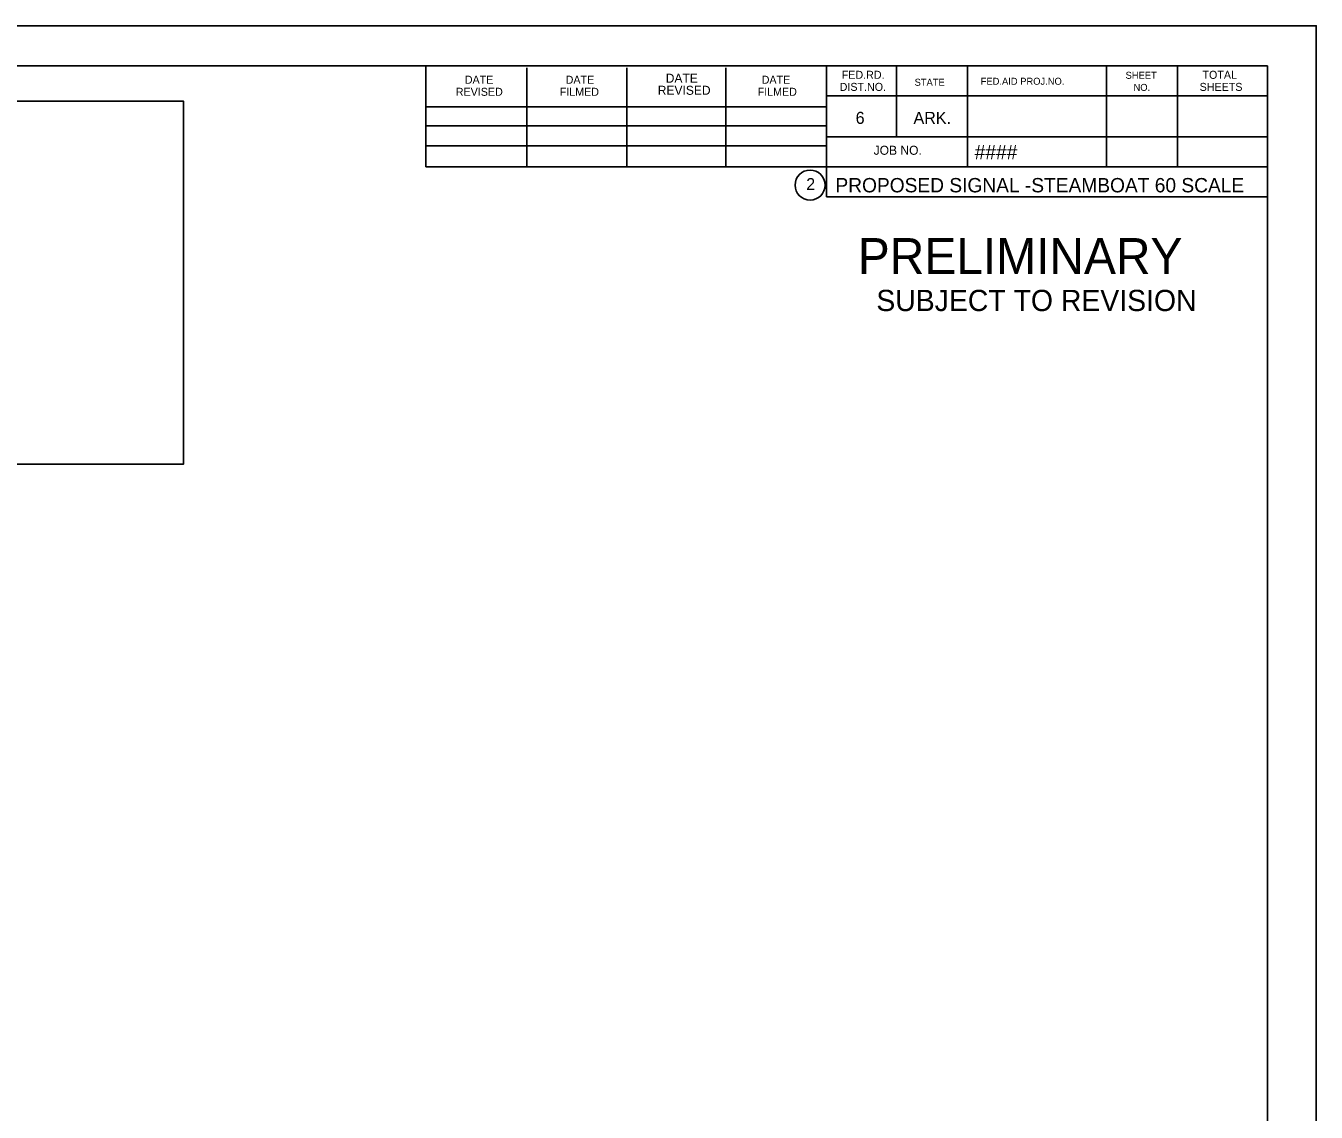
# Model space of a CAD drawing. Extents: x 660636 to 661659, y 641779 to 643841.
# Drawn here: x 661280.2 to 661658.6, y 642605.7 to 642924 of the extents above; entities that cross this region are included whole.
import ezdxf

# ---------------------------------------------------------------- set-up
doc = ezdxf.new("R2010")
doc.units = 0
for name, color, linetype in [('Default', 7, 'Continuous'), ('R_Border', 7, 'Continuous'), ('R_Border Prem', 7, 'Continuous'), ('R_No Plot', 7, 'Continuous')]:
    doc.layers.add(name, color=color, linetype=linetype)

msp = doc.modelspace()

# ---------------------------------------------------------------- linework, layer by layer
at = {"layer": 'Default'}
msp.add_lwpolyline([(661077.35, 642795.58), (661326.48, 642795.58), (661326.48, 642901.91), (661077.35, 642901.91)], close=True, dxfattribs=at)
at = {"layer": 'R_Border'}
for p, q in [((660695.76, 642912.31), (661644.3, 642912.31)), ((661397.52, 642882.67), (661397.52, 642912.31)), ((661427.09, 642882.67), (661427.09, 642911.71)), ((661456.38, 642882.67), (661456.38, 642911.71)), ((661485.42, 642882.67), (661485.42, 642911.71)), ((661514.99, 642912.31), (661514.99, 642873.91)), ((661535.52, 642912.31), (661535.52, 642891.49)), ((661556.33, 642912.31), (661556.33, 642882.67)), ((661597.08, 642912.31), (661597.08, 642882.67)), ((661617.9, 642912.31), (661617.9, 642882.67)), ((661644.3, 642295.93), (661644.3, 642912.31)), ((661644.3, 642903.49), (661514.99, 642903.49)), ((661644.3, 642903.55), (661644.3, 642903.55)), ((661397.52, 642900.25), (661514.99, 642900.25)), ((661397.52, 642894.67), (661514.99, 642894.67)), ((661644.3, 642891.49), (661514.99, 642891.49)), ((661523.88, 642891.49), (661644.3, 642891.49)), ((661397.52, 642882.67), (661397.52, 642888.85)), ((661397.52, 642888.85), (661514.99, 642888.85)), ((661644.3, 642882.67), (661397.52, 642882.67)), ((661514.99, 642873.91), (661644.3, 642873.91))]:
    msp.add_line(p, q, dxfattribs=at)
msp.add_circle((661510.16, 642877.32), 4.4, dxfattribs=at)
at = {"layer": 'R_No Plot'}
msp.add_line((660658.55, 642924), (661658.55, 642924), dxfattribs=at)
msp.add_lwpolyline([(660658.53, 642924), (661658.55, 642924), (661658.55, 642283.98), (660658.53, 642283.98)], close=True, dxfattribs=at)

# ---------------------------------------------------------------- texts
at = {"layer": 'R_Border'}
for s, height, p in [('FED.RD.', 2.346, (661519.44, 642908.47)), ('SHEET', 2.052, (661602.66, 642908.47)), ('TOTAL', 2.346, (661625.21, 642908.47)), ('DATE', 2.346, (661408.92, 642907.03)), ('DATE', 2.346, (661438.49, 642907.03)), ('REVISED', 2.638, (661465.49, 642903.79)), ('DATE', 2.638, (661467.83, 642907.33)), ('DATE', 2.346, (661495.97, 642907.03)), ('DIST.NO.', 2.346, (661518.83, 642904.93)), ('STATE', 2.052, (661540.8, 642906.43)), ('FED.AID PROJ.NO.', 2.052, (661560.18, 642906.73)), ('NO.', 2.052, (661604.99, 642904.93)), ('SHEETS', 2.346, (661624.38, 642904.93)), ('REVISED', 2.346, (661406.28, 642903.49)), ('FILMED', 2.346, (661436.76, 642903.49)), ('FILMED', 2.346, (661494.78, 642903.49)), ('6', 3.52, (661523.52, 642895.27)), ('ARK.', 3.517, (661540.49, 642895.27)), ('JOB NO.', 2.638, (661528.8, 642886.21)), ('####', 4.2, (661558.42, 642884.89)), ('2', 3.52, (661509.01, 642875.86)), ('PROPOSED SIGNAL -STEAMBOAT 60 SCALE', 4.2, (661517.59, 642875.2))]:
    msp.add_text(s, height=height, rotation=360, dxfattribs=at).set_placement(p)
at = {"layer": 'R_Border Prem'}
for s, height, p in [('PRELIMINARY', 10.5, (661524.15, 642851.3)), ('SUBJECT TO REVISION', 6.2253, (661529.58, 642840.41))]:
    msp.add_text(s, height=height, rotation=360, dxfattribs=at).set_placement(p)

doc.saveas('drawing.dxf')
